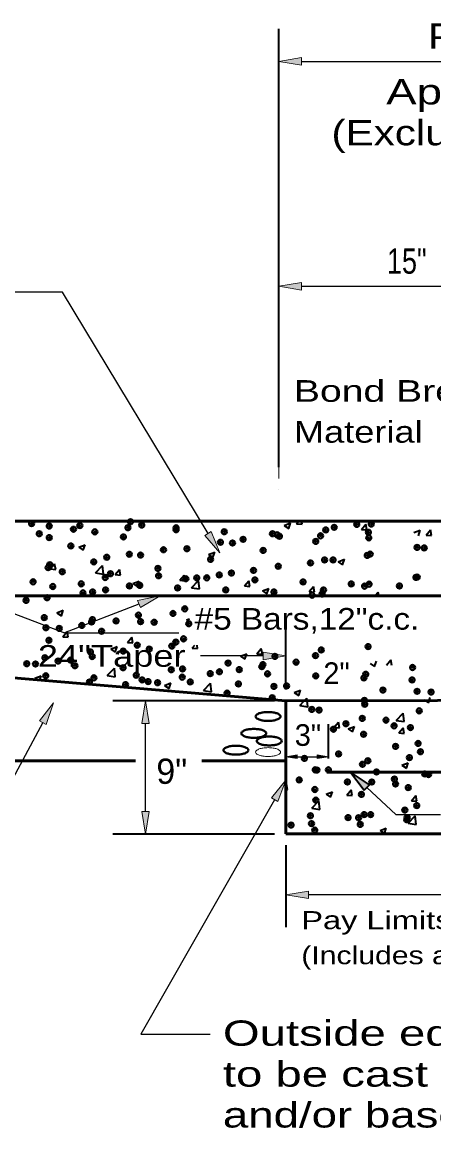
# Model space of a CAD drawing. Extents: x 36.4 to 71.7, y 0.5 to 22.5.
# Drawn here: x 44.62 to 46.9, y 6.74 to 12.87 of the extents above; entities that cross this region are included whole.
import ezdxf

# ---------------------------------------------------------------- set-up
doc = ezdxf.new("R2010")
doc.units = 0
doc.header["$LTSCALE"] = 0.056
doc.header["$PDMODE"] = 32
doc.header["$PDSIZE"] = 0.028
for name, color, linetype, lineweight in [('1', 7, 'Continuous', 40), ('3', 7, 'Continuous', 13), ('6', 7, 'Continuous', 13)]:
    doc.layers.add(name, color=color, linetype=linetype, lineweight=lineweight)

msp = doc.modelspace()

# ---------------------------------------------------------------- hatches: boundary and pattern name
at = {"layer": '1'}
for points in [[(46.16342, 12.63425), (46.16342, 12.67592), (46.03842, 12.65508), (46.03842, 12.65508)], [(46.16342, 11.38717), (46.16342, 11.42883), (46.03842, 11.408), (46.03842, 11.408)], [(45.95133, 9.3385), (45.95133, 9.38017), (46.07633, 9.35925), (46.07633, 9.35925)], [(45.31942, 8.98483), (45.27775, 8.98483), (45.29858, 9.10983), (45.29858, 9.10983)], [(46.13883, 8.79), (46.13883, 8.81083), (46.07633, 8.80033), (46.07633, 8.80033)], [(46.24958, 8.79), (46.24958, 8.81083), (46.31208, 8.80033), (46.31208, 8.80033)], [(45.31942, 8.49717), (45.27775, 8.49717), (45.29858, 8.37217), (45.29858, 8.37217)], [(46.20133, 8.01433), (46.20133, 8.056), (46.07633, 8.03508), (46.07633, 8.03508)]]:
    msp.add_hatch(color=256, dxfattribs=at).paths.add_polyline_path(points)
at = {"layer": '3'}
for points in [[(45.663, 10.04875), (45.62742, 10.02708), (45.70983, 9.93092), (45.70983, 9.93092)], [(45.25525, 9.66625), (45.27025, 9.62742), (45.37933, 9.69192), (45.37933, 9.69192)], [(44.71117, 8.99942), (44.74783, 8.97967), (44.78867, 9.09967), (44.78867, 9.09967)], [(46.5115, 8.61475), (46.53992, 8.64525), (46.43425, 8.71517), (46.43425, 8.71517)], [(45.99633, 8.5725), (46.0325, 8.55175), (46.07633, 8.67075), (46.07633, 8.67075)]]:
    msp.add_hatch(color=256, dxfattribs=at).paths.add_polyline_path(points)

# ---------------------------------------------------------------- linework, layer by layer
at = {"layer": '1', "lineweight": 35}
for p, q in [((46.03842, 10.40533), (46.03842, 12.83508)), ((45.37417, 10.10608), (45.37433, 10.106)), ((45.37433, 10.106), (45.37442, 10.10608)), ((46.06808, 10.08267), (46.10308, 10.09617)), ((46.06808, 10.08267), (46.09292, 10.06592)), ((46.09292, 10.06592), (46.10308, 10.09617)), ((46.13633, 10.09225), (46.148, 10.10608)), ((46.13633, 10.09225), (46.16625, 10.08958)), ((46.16625, 10.08958), (46.16317, 10.10608)), ((46.495, 10.06083), (46.51908, 10.08958)), ((46.495, 10.06083), (46.52483, 10.05825)), ((46.52492, 10.05825), (46.51908, 10.08958)), ((46.78658, 10.04267), (46.82158, 10.05608)), ((46.8115, 10.02583), (46.82167, 10.05608)), ((46.85358, 10.0295), (46.87775, 10.05817)), ((46.8835, 10.02683), (46.87775, 10.05817)), ((46.85358, 10.0295), (46.8835, 10.02683)), ((44.92933, 9.9615), (44.96442, 9.97492)), ((44.92933, 9.9615), (44.95425, 9.94467)), ((44.95425, 9.94467), (44.96442, 9.97492)), ((45.64792, 9.92142), (45.68292, 9.93483)), ((45.67283, 9.90467), (45.68292, 9.93483)), ((44.77117, 9.84167), (44.79533, 9.87033)), ((44.80108, 9.839), (44.79533, 9.87033)), ((45.64792, 9.92142), (45.67283, 9.90467)), ((46.3665, 9.88142), (46.4015, 9.89483)), ((46.3665, 9.88142), (46.39133, 9.86458)), ((46.39142, 9.86458), (46.4015, 9.89483)), ((44.77117, 9.84167), (44.80108, 9.839)), ((45.02083, 9.82008), (45.05975, 9.86067)), ((45.02083, 9.82008), (45.06533, 9.81317)), ((45.06533, 9.81317), (45.05975, 9.86067)), ((45.12983, 9.81025), (45.15392, 9.839)), ((45.12983, 9.81025), (45.15975, 9.80767)), ((45.15975, 9.80767), (45.15392, 9.839)), ((45.4885, 9.77892), (45.51258, 9.80758)), ((45.51833, 9.77625), (45.51258, 9.80758)), ((45.22783, 9.76017), (45.26283, 9.77358)), ((45.22783, 9.76017), (45.25267, 9.74342)), ((45.25267, 9.74342), (45.26283, 9.77358)), ((45.4885, 9.77892), (45.51833, 9.77625)), ((45.55442, 9.73733), (45.59342, 9.77792)), ((45.59892, 9.73042), (45.59342, 9.77792)), ((45.84708, 9.7475), (45.87117, 9.77625)), ((45.84708, 9.7475), (45.877, 9.74492)), ((45.877, 9.74492), (45.87125, 9.77625)), ((45.55442, 9.73733), (45.59892, 9.73042)), ((45.94642, 9.72017), (45.98142, 9.73358)), ((45.94642, 9.72017), (45.97125, 9.70333)), ((45.97125, 9.70333), (45.98142, 9.73358)), ((46.12542, 9.6935), (46.127, 9.69517)), ((46.12725, 9.6935), (46.127, 9.69517)), ((46.20575, 9.71617), (46.22983, 9.74483)), ((46.20575, 9.71617), (46.23558, 9.7135)), ((46.23558, 9.7135), (46.22983, 9.74483)), ((46.57167, 9.6935), (46.5885, 9.7135)), ((46.59217, 9.6935), (46.5885, 9.7135)), ((46.69983, 9.6935), (46.7, 9.6935)), ((46.69992, 9.6935), (46.7, 9.6935)), ((44.80775, 9.59892), (44.84275, 9.61233)), ((44.80775, 9.59892), (44.83258, 9.58217)), ((44.83258, 9.58208), (44.84275, 9.61233)), ((45.52625, 9.55883), (45.54258, 9.56508)), ((45.52625, 9.55883), (45.54258, 9.54783)), ((46.07633, 9.17242), (46.07633, 9.53933)), ((44.84058, 9.4655), (44.86467, 9.49425)), ((44.84058, 9.4655), (44.8705, 9.46292)), ((44.8705, 9.46292), (44.86467, 9.49425)), ((45.19925, 9.43417), (45.22333, 9.46292)), ((45.22908, 9.4315), (45.22333, 9.46292)), ((45.10617, 9.39758), (45.14117, 9.411)), ((45.10617, 9.39758), (45.131, 9.38083)), ((45.10617, 9.39758), (45.131, 9.38083)), ((45.13108, 9.38083), (45.14117, 9.411)), ((45.19925, 9.43417), (45.22908, 9.43158)), ((45.55783, 9.40275), (45.57158, 9.41917)), ((45.55783, 9.40275), (45.58775, 9.40017)), ((45.58775, 9.40017), (45.58425, 9.41917)), ((45.9165, 9.37142), (45.94058, 9.40017)), ((45.94633, 9.36875), (45.94058, 9.40017)), ((45.82475, 9.35758), (45.85975, 9.371)), ((45.82475, 9.35758), (45.84958, 9.34075)), ((45.84958, 9.34075), (45.85975, 9.371)), ((45.9165, 9.37142), (45.94633, 9.36883)), ((46.54333, 9.3175), (46.56817, 9.30075)), ((46.56817, 9.30075), (46.57833, 9.33092)), ((46.63375, 9.30867), (46.65783, 9.33742)), ((46.66367, 9.306), (46.65783, 9.33733)), ((45.08717, 9.25025), (45.12608, 9.29083)), ((45.13158, 9.24333), (45.12608, 9.29083)), ((44.68608, 9.23633), (44.72108, 9.24975)), ((44.68608, 9.23633), (44.70133, 9.226)), ((44.71275, 9.22508), (44.72108, 9.24975)), ((45.08717, 9.25025), (45.13158, 9.24333)), ((45.40458, 9.19625), (45.43967, 9.20975)), ((45.40458, 9.19625), (45.4295, 9.1795)), ((45.4295, 9.1795), (45.43967, 9.20975)), ((45.62075, 9.1675), (45.65967, 9.20808)), ((45.66525, 9.16058), (45.65967, 9.20808)), ((45.62075, 9.1675), (45.66525, 9.16058)), ((46.12317, 9.15625), (46.15817, 9.16967)), ((46.12317, 9.15625), (46.14808, 9.1395)), ((46.14808, 9.13942), (46.15817, 9.16967)), ((46.01383, 9.10992), (45.11858, 9.10992)), ((46.15433, 9.08475), (46.17883, 9.11025)), ((46.15433, 9.08475), (46.19883, 9.07783)), ((46.17883, 9.11025), (46.19333, 9.12533)), ((46.19508, 9.11033), (46.19333, 9.12533)), ((46.19883, 9.07783), (46.19508, 9.11033)), ((46.19883, 9.07783), (46.19508, 9.11033)), ((46.84175, 9.11617), (46.84842, 9.11167)), ((46.84842, 9.11167), (46.86658, 9.09942)), ((46.86667, 9.09942), (46.87075, 9.11175)), ((46.87075, 9.11175), (46.87675, 9.12967)), ((46.688, 9.002), (46.72692, 9.04258)), ((46.7325, 8.99508), (46.72692, 9.04258)), ((46.31208, 8.79017), (46.31208, 8.98042)), ((46.3445, 8.96392), (46.36858, 8.99267)), ((46.3445, 8.96392), (46.37433, 8.96133)), ((46.37433, 8.96133), (46.36858, 8.99267)), ((46.42167, 8.95492), (46.45667, 8.96833)), ((46.42167, 8.95492), (46.4465, 8.93817)), ((46.4465, 8.93817), (46.45667, 8.96833)), ((46.688, 9.002), (46.73242, 8.99508)), ((46.70308, 8.93258), (46.72725, 8.96125)), ((46.733, 8.92992), (46.72725, 8.96125)), ((46.70308, 8.93258), (46.733, 8.92992)), ((46.72008, 8.75358), (46.75508, 8.76708)), ((46.745, 8.73683), (46.75508, 8.76708)), ((46.72008, 8.75358), (46.745, 8.73683)), ((46.07633, 8.64433), (46.07933, 8.64792)), ((46.08508, 8.61658), (46.07933, 8.64792)), ((46.07633, 8.61733), (46.08508, 8.61658)), ((46.3, 8.59233), (46.335, 8.60583)), ((46.3, 8.59233), (46.32483, 8.57558)), ((46.32483, 8.57558), (46.335, 8.60575)), ((46.41383, 8.58783), (46.438, 8.61658)), ((46.41383, 8.58783), (46.44375, 8.58525)), ((46.44375, 8.58525), (46.438, 8.61658)), ((46.7725, 8.5565), (46.79658, 8.58517)), ((46.80242, 8.55383), (46.79658, 8.58517)), ((46.22067, 8.51492), (46.25958, 8.5555)), ((46.26517, 8.508), (46.25958, 8.5555)), ((46.7725, 8.5565), (46.80233, 8.55383)), ((46.22067, 8.51492), (46.26517, 8.508)), ((46.75425, 8.43217), (46.79325, 8.47275)), ((46.79875, 8.42525), (46.79325, 8.47275)), ((46.59842, 8.39108), (46.63342, 8.4045)), ((46.62333, 8.37425), (46.63342, 8.4045)), ((46.75425, 8.43217), (46.79875, 8.42525)), ((46.01383, 8.37217), (45.11858, 8.37217)), ((46.59842, 8.39108), (46.62333, 8.37425)), ((46.07633, 8.30967), (46.07633, 7.85517))]:
    msp.add_line(p, q, dxfattribs=at)
at = {"layer": '1', "lineweight": 25}
for p, q in [((46.16342, 12.65508), (49.90942, 12.65508)), ((46.16342, 11.408), (47.39025, 11.408)), ((45.95133, 9.35933), (45.60433, 9.35933)), ((45.29858, 8.49717), (45.29858, 8.98492)), ((46.13883, 8.80042), (46.24958, 8.80042)), ((49.91308, 8.03517), (46.20133, 8.03517))]:
    msp.add_line(p, q, dxfattribs=at)
at = {"layer": '1', "lineweight": 13}
for p, q in [((46.03842, 10.34283), (46.03842, 11.588)), ((46.07633, 8.75117), (46.07633, 8.62042))]:
    msp.add_line(p, q, dxfattribs=at)
at = {"layer": '1', "lineweight": 53}
for p, q in [((47.36392, 9.69192), (43.57042, 9.69192)), ((46.07633, 9.11), (46.07633, 8.37225)), ((45.61158, 8.7775), (46.07633, 8.7775)), ((49.75083, 8.71517), (46.304, 8.71517)), ((50.03808, 8.37225), (46.07633, 8.37225))]:
    msp.add_line(p, q, dxfattribs=at)
at = {"layer": '1', "lineweight": 13}
for points in [[(46.16342, 12.63425), (46.16342, 12.67592), (46.03842, 12.65508), (46.03842, 12.65508)], [(46.16342, 11.38717), (46.16342, 11.42883), (46.03842, 11.408), (46.03842, 11.408)], [(45.95133, 9.3385), (45.95133, 9.38017), (46.07633, 9.35925), (46.07633, 9.35925)], [(45.31942, 8.98483), (45.27775, 8.98483), (45.29858, 9.10983), (45.29858, 9.10983)], [(46.13883, 8.79), (46.13883, 8.81083), (46.07633, 8.80033), (46.07633, 8.80033)], [(46.24958, 8.79), (46.24958, 8.81083), (46.31208, 8.80033), (46.31208, 8.80033)], [(45.31942, 8.49717), (45.27775, 8.49717), (45.29858, 8.37217), (45.29858, 8.37217)], [(46.20133, 8.01433), (46.20133, 8.056), (46.07633, 8.03508), (46.07633, 8.03508)]]:
    msp.add_lwpolyline(points, close=True, dxfattribs=at)
at = {"layer": '1', "lineweight": 53}
for points in [[(47.51525, 10.10608), (43.59017, 10.10608), (43.59017, 9.827), (43.43175, 9.55683), (43.67933, 9.42175), (43.62983, 9.27633), (44.10525, 9.27633), (46.07633, 9.11), (53.64175, 9.12625)], [(43.62983, 9.27633), (43.57042, 9.23475), (43.57042, 8.7775), (45.24308, 8.7775)]]:
    msp.add_lwpolyline(points, dxfattribs=at)
at = {"layer": '1'}
for centre, radius, start, end in [((45.91933, 9.02358), 0.01016, 130.3333, 179.56474), ((45.91942, 9.02367), 0.01025, 180.19847, 229.42992), ((45.947, 9.05583), 0.05258, 229.32889, 250.44364), ((45.94725, 8.9915), 0.05269, 109.77026, 130.885), ((45.96592, 8.9395), 0.10795, 98.52638, 109.76521), ((45.97817, 8.85525), 0.19304, 90.0102, 98.42523), ((45.97808, 8.85583), 0.19248, 81.56233, 89.97736), ((45.99033, 8.93908), 0.10836, 70.28977, 81.5286), ((46.00908, 8.9915), 0.05269, 49.11499, 70.22974), ((46.00933, 9.05583), 0.05258, 289.55636, 310.6711), ((46.037, 9.02367), 0.01012, 359.922, 49.15345), ((46.03692, 9.02358), 0.01021, 311.07972, 0.31117), ((45.88625, 8.84592), 0.10785, 98.30717, 109.546), ((45.89892, 8.76167), 0.19304, 90.0102, 98.42523), ((45.89883, 8.76225), 0.19248, 81.56233, 89.97736), ((45.91158, 8.8455), 0.10826, 70.5082, 81.74703), ((45.96592, 9.10783), 0.10795, 250.23479, 261.47362), ((45.97817, 9.19208), 0.19304, 261.57477, 269.98979), ((45.97808, 9.1915), 0.19248, 270.02264, 278.43766), ((45.99033, 9.10825), 0.10836, 278.47139, 289.71023), ((45.84008, 8.93008), 0.01016, 130.3333, 179.56474), ((45.84017, 8.93017), 0.01025, 180.19847, 229.42992), ((45.86775, 8.96233), 0.05258, 229.32889, 250.44364), ((45.868, 8.898), 0.05269, 109.77026, 130.885), ((45.88667, 9.01433), 0.10795, 250.23479, 261.47362), ((45.89892, 9.09858), 0.19304, 261.57477, 269.98979), ((45.89883, 9.098), 0.19248, 270.02264, 278.43766), ((45.92592, 8.88783), 0.01021, 131.07972, 180.31117), ((45.92583, 8.88775), 0.01012, 179.922, 229.15345), ((45.9535, 8.85558), 0.05258, 109.55636, 130.6711), ((45.91108, 9.01475), 0.10836, 278.47139, 289.71023), ((45.9725, 8.80317), 0.10836, 98.47139, 109.71022), ((45.92983, 8.898), 0.05269, 49.11499, 70.22974), ((45.93008, 8.96233), 0.05258, 289.55636, 310.6711), ((45.98475, 8.71933), 0.19304, 90.0102, 98.42523), ((45.95775, 8.93017), 0.01012, 359.922, 49.15345), ((45.95767, 8.93008), 0.01021, 311.07972, 0.31117), ((45.98467, 8.71992), 0.19248, 81.56233, 89.97736), ((45.99692, 8.80317), 0.10836, 70.28977, 81.5286), ((46.01592, 8.85558), 0.05258, 49.32889, 70.44364), ((46.04358, 8.88775), 0.01012, 310.84655, 0.07799), ((46.0435, 8.88783), 0.01021, 359.68883, 48.92027), ((45.74108, 8.83667), 0.01021, 131.07972, 180.31117), ((45.741, 8.83658), 0.01012, 179.922, 229.15345), ((45.76867, 8.80442), 0.05258, 109.55636, 130.6711), ((45.76892, 8.86875), 0.05269, 229.11499, 250.22974), ((45.78767, 8.752), 0.10836, 98.47139, 109.71022), ((45.79992, 8.66875), 0.19248, 90.02264, 98.43766), ((45.79983, 8.66817), 0.19304, 81.57477, 89.98979), ((45.81208, 8.75242), 0.10795, 70.23479, 81.47362), ((45.83075, 8.86875), 0.05269, 289.77026, 310.885), ((45.831, 8.80442), 0.05258, 49.32889, 70.44364), ((45.85858, 8.83658), 0.01025, 0.19847, 49.42992), ((45.85867, 8.83667), 0.01016, 310.3333, 359.56474), ((45.95375, 8.91992), 0.05269, 229.11499, 250.22974), ((45.972, 8.97242), 0.10826, 250.5082, 261.74703), ((45.98475, 9.05625), 0.19304, 261.57477, 269.98979), ((45.98467, 9.05567), 0.19248, 270.02264, 278.43766), ((45.99742, 8.97242), 0.10826, 278.25297, 289.4918), ((46.01567, 8.91992), 0.05269, 289.77026, 310.885), ((45.78717, 8.92125), 0.10826, 250.5082, 261.74703), ((45.79992, 9.0045), 0.19248, 261.56233, 269.97736), ((45.79983, 9.00508), 0.19304, 270.0102, 278.42523), ((45.8125, 8.92083), 0.10785, 278.30717, 289.546)]:
    msp.add_arc(centre, radius, start, end, dxfattribs=at)
at = {"layer": '1', "lineweight": 13}
for centre, radius, start, end in [((45.91933, 8.82617), 0.01016, 130.3333, 179.56474), ((45.94725, 8.79408), 0.05269, 109.77026, 130.885), ((45.9655, 8.742), 0.10785, 98.30717, 109.546), ((45.97817, 8.65775), 0.19304, 90.0102, 98.42523), ((45.97808, 8.65833), 0.19248, 81.56233, 89.97736), ((45.99083, 8.74158), 0.10826, 70.5082, 81.74703), ((46.00908, 8.79408), 0.05269, 49.11499, 70.22974), ((46.037, 8.82625), 0.01012, 359.922, 49.15345), ((45.91942, 8.82625), 0.01025, 180.19847, 229.42992), ((45.947, 8.85842), 0.05258, 229.32889, 250.44364), ((45.96592, 8.91042), 0.10795, 250.23479, 261.47362), ((45.97817, 8.99467), 0.19304, 261.57477, 269.98979), ((45.97808, 8.99408), 0.19248, 270.02264, 278.43766), ((45.99033, 8.91083), 0.10836, 278.47139, 289.71023), ((46.00933, 8.85842), 0.05258, 289.55636, 310.6711), ((46.03692, 8.82617), 0.01021, 311.07972, 0.31117)]:
    msp.add_arc(centre, radius, start, end, dxfattribs=at)
at = {"layer": '1'}
for p in [(45.2155, 10.10333), (44.66783, 10.09275), (44.76517, 10.07892), (44.89975, 10.06175), (44.93475, 10.0815), (45.01808, 10.047), (45.20167, 10.07017), (45.27775, 10.0845), (45.46817, 10.06917), (45.46858, 10.05892), (45.7355, 10.04767), (46.29733, 10.05792), (46.34458, 10.07208), (46.46975, 10.08858), (46.53392, 10.04442), (46.54992, 10.08992), (44.71033, 10.03683), (44.7655, 10.015), (45.17658, 10.01917), (45.71425, 9.98908), (45.78092, 9.98525), (45.83942, 10.00558), (46.00242, 10.03633), (46.02883, 10.0305), (46.04067, 10.02275), (46.24233, 9.99433), (46.26933, 10.02508), (46.53625, 10.01383), (44.885, 9.96908), (45.20917, 9.92258), (45.27167, 9.918), (45.3985, 9.94758), (45.52842, 9.95325), (45.95075, 9.94425), (46.52758, 9.91633), (46.54383, 9.9235), (46.8035, 9.961), (46.84333, 9.95792), (44.76817, 9.86458), (45.012, 9.88058), (45.084, 9.90617), (45.65917, 9.89425), (46.03458, 9.85625), (46.21308, 9.87492), (46.29125, 9.8915), (46.33825, 9.89133), (44.75942, 9.8485), (44.83742, 9.826), (45.076, 9.79408), (45.10433, 9.81467), (45.36758, 9.84417), (45.37125, 9.80342), (45.70792, 9.80842), (45.77483, 9.81883), (45.89725, 9.83333), (46.79742, 9.79458), (46.80492, 9.79608), (44.67592, 9.77008), (44.78442, 9.74408), (44.94283, 9.75883), (45.20975, 9.7475), (45.26558, 9.75158), (45.267, 9.75033), (45.47667, 9.73625), (45.52233, 9.78683), (45.58275, 9.79192), (45.63817, 9.79217), (45.90508, 9.78083), (46.172, 9.76958), (46.43883, 9.75833), (46.51325, 9.74608), (46.53775, 9.75708), (46.70575, 9.747), (44.75333, 9.68208), (44.95242, 9.70892), (45.00592, 9.71408), (45.07758, 9.72542), (45.74358, 9.725), (46.0105, 9.71367), (46.22167, 9.696), (46.27742, 9.70242), (46.28517, 9.72508), (44.63667, 9.66733), (45.51625, 9.62033), (44.73792, 9.57183), (45.00483, 9.56058), (45.13542, 9.55317), (45.2595, 9.58517), (45.27175, 9.54925), (45.45117, 9.59467), (44.74725, 9.51567), (44.82092, 9.51175), (44.94608, 9.52817), (44.99983, 9.54767), (45.05533, 9.49575), (45.34692, 9.54583), (45.53867, 9.538), (44.76375, 9.44575), (45.46675, 9.43608), (45.51017, 9.45392), (44.99375, 9.38117), (45.17517, 9.386), (45.25342, 9.41867), (45.31967, 9.3975), (45.44483, 9.414), (46.273, 9.39217), (46.5325, 9.41125), (44.64058, 9.31633), (44.68933, 9.3145), (44.74117, 9.34917), (44.8145, 9.331), (44.8835, 9.33592), (44.9075, 9.30508), (45.00392, 9.35592), (45.75658, 9.3195), (45.94925, 9.31117), (46.01633, 9.35692), (46.133, 9.32467), (46.24083, 9.36117), (44.746, 9.24917), (45.17442, 9.29375), (45.24733, 9.25225), (45.44133, 9.2825), (45.50267, 9.24167), (45.50408, 9.28742), (45.65767, 9.26108), (45.70817, 9.27125), (45.81842, 9.28325), (45.94358, 9.29975), (45.97508, 9.25992), (46.242, 9.24867), (46.5195, 9.25775), (46.77917, 9.29517), (44.98767, 9.21475), (45.01292, 9.23792), (45.18817, 9.20033), (45.27983, 9.22658), (45.31333, 9.21675), (45.36608, 9.211), (45.54675, 9.21533), (45.81367, 9.20408), (46.01025, 9.1905), (46.0805, 9.19275), (46.50892, 9.23742), (46.77583, 9.22608), (45.75058, 9.153), (46.00142, 9.1275), (46.61433, 9.17025), (46.80342, 9.163), (46.88125, 9.15892), (46.22025, 9.06283), (46.26092, 9.05925), (46.51183, 9.11292), (46.51342, 9.09125), (46.50025, 9.01325), (46.63158, 9.00308), (46.816, 9.05483), (46.34, 8.95308), (46.4095, 8.98325), (46.67633, 8.97192), (46.76708, 8.96233), (46.50733, 8.92483), (46.80967, 8.87408), (46.36867, 8.81608), (46.6845, 8.85758), (46.82258, 8.82817), (46.17933, 8.79108), (46.50125, 8.75842), (46.531, 8.77808), (46.761, 8.79583), (46.23942, 8.728), (46.24875, 8.72633), (46.31208, 8.72775), (46.579, 8.71642), (46.84592, 8.70517), (46.8675, 8.70183), (46.15058, 8.67183), (46.4175, 8.66058), (46.55292, 8.66042), (46.67808, 8.67692), (46.68442, 8.64933), (46.75492, 8.62942), (46.23717, 8.61883), (46.49517, 8.59192), (46.24267, 8.55992), (46.80192, 8.52983), (46.21258, 8.47358), (46.42142, 8.46325), (46.4795, 8.46233), (46.51033, 8.47975), (46.54658, 8.47967), (46.73592, 8.50458), (46.74642, 8.451), (46.74883, 8.463), (46.10558, 8.42167), (46.21875, 8.42975), (46.23658, 8.3935), (46.48908, 8.4255)]:
    msp.add_point(p, dxfattribs=at)
at = {"layer": '3', "lineweight": 25}
msp.add_line((45.26275, 9.64683), (44.84925, 9.48683), dxfattribs=at)
for points in [[(45.64525, 10.03792), (44.83817, 11.37533), (43.47133, 11.37533)], [(44.426, 9.64758), (44.84925, 9.48683), (45.48417, 9.48683)], [(44.7295, 8.98958), (44.35283, 8.28917), (43.99625, 8.28917)], [(46.52567, 8.63), (46.68658, 8.48008), (46.93275, 8.48008)], [(46.01442, 8.56217), (45.27333, 7.26208), (45.65692, 7.26208)]]:
    msp.add_lwpolyline(points, dxfattribs=at)
at = {"layer": '3'}
for points in [[(45.663, 10.04875), (45.62742, 10.02708), (45.70983, 9.93092), (45.70983, 9.93092)], [(45.25525, 9.66625), (45.27025, 9.62742), (45.37933, 9.69192), (45.37933, 9.69192)], [(44.71117, 8.99942), (44.74783, 8.97967), (44.78867, 9.09967), (44.78867, 9.09967)], [(45.99633, 8.5725), (46.0325, 8.55175), (46.07633, 8.67075), (46.07633, 8.67075)]]:
    msp.add_lwpolyline(points, close=True, dxfattribs=at)
at = {"layer": '3', "lineweight": 35}
msp.add_lwpolyline([(46.5115, 8.61475), (46.53992, 8.64525), (46.43425, 8.71517), (46.43425, 8.71517)], close=True, dxfattribs=at)
at = {"layer": '6'}
for p, q in [((46.03842, 10.34283), (46.0385, 10.34283)), ((46.03842, 10.28033), (46.0385, 10.28033)), ((45.29858, 9.10992), (45.29867, 9.10992)), ((46.07633, 9.10992), (46.07642, 9.10992)), ((46.07633, 9.10992), (46.07642, 9.10992)), ((46.07633, 8.81367), (46.07642, 8.81367)), ((46.31208, 8.80042), (46.31217, 8.80042)), ((46.31208, 8.72767), (46.31217, 8.72767)), ((46.07633, 8.37217), (46.07642, 8.37217)), ((46.07633, 8.37217), (46.07642, 8.37217)), ((46.07633, 8.03517), (46.07642, 8.03517))]:
    msp.add_line(p, q, dxfattribs=at)

# ---------------------------------------------------------------- texts
at = {"layer": '1'}
for s, height, width, p in [('Pay Limits For Bridge', 0.14, 1.3, (46.86308, 12.72508)), ('15"', 0.14, 0.8, (46.63683, 11.478)), ('24"Taper', 0.12, 1.25, (44.70225, 9.29933))]:
    msp.add_text(s, height=height, dxfattribs=dict(at, width=width)).set_placement(p)
at = {"layer": '3'}
for s, height, width, p in [('Approach Expansion Joint', 0.14, 1.35, (46.63275, 12.41633)), ('(Excluding Bituminous Overlay)', 0.14, 1.25, (46.32925, 12.18967)), ('Bond Breaking', 0.12, 1.35, (46.12125, 10.76792)), ('Material', 0.12, 1.25, (46.12125, 10.54125)), ('#5 Bars,12"c.c.', 0.12, 1.15, (45.57117, 9.50492)), ('Pay Limits For Bridge Approach Expansion Joint', 0.1, 1.35, (46.16208, 7.84458)), ('(Includes all #4 and #5 Bars Shown above)', 0.1, 1.25, (46.16208, 7.65033)), ('Outside edges and bottom of subslab', 0.14, 1.4, (45.72758, 7.1985)), ('to be cast against compacted subgrade', 0.14, 1.4, (45.72758, 6.97183)), ('and/or base material without forms.', 0.14, 1.35, (45.72758, 6.74517))]:
    msp.add_text(s, height=height, dxfattribs=dict(at, width=width)).set_placement(p)
for s, height, p in [('2"', 0.12, (46.28433, 9.20358)), ('3"', 0.12, (46.12583, 8.86067)), ('9"', 0.14, (45.35917, 8.65025))]:
    msp.add_text(s, height=height, dxfattribs=at).set_placement(p)

doc.saveas('drawing.dxf')
